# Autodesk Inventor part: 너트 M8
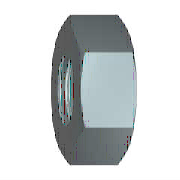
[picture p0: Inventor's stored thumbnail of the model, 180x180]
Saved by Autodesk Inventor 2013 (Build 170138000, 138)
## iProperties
IsCustomPart: 1
Created: 2012-02
Part Number: 너트 M8
Material: 강철, 연강
Description: 6각 너트 및 6각 가는 너트
Document SubType Name: Modeling
Standard: KS B 1012
Designer: mduedu
Standards Organization: KS
Language: ko-KR
Size Designation: M 8
Categories: <MemberInstance><Categories><Category DisplayName="조임쇠" InternalName="e4da775c-781d-43d5-af7c-5136215cf5a6" Mnemonic="FSTN"><Category DisplayName="너트" InternalN
Density: 1 g/cm^3
Author: mduedu
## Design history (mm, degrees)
sketch "스케치1"
  geometry: L1 (-7.506, 0)-(-3.753, 6.5); L2 (-3.753, 6.5)-(3.753, 6.5); L3 (3.753, 6.5)-(7.506, 0); L4 (7.506, 0)-(3.753, -6.5); L5 (3.753, -6.5)-(-3.753, -6.5); L6 (-3.753, -6.5)-(-7.506, 0); 2 further points
  constraints: 12 end point, 1 coincident, 1 horizontal, 11 other
  dimensions: "d0" = 15.01111 distance of L3.end L1.start (= 1.1547 x SW)
extrude "본체" new body sketch "스케치1" distance "d1" = 5 (= KOH); taper "d2" = 0 deg
sketch "스케치2"
  geometry: L1 (0, 3.753)-(0, 7.506) reference; L2 (0, 7.506)-(5, 7.506) reference; L3 (5, 3.753)-(5, 7.506) reference; L4 (-1, 0)-(6, 0) reference; L5 (0.581, 7.506)-(0, 6.5); L6 (4.419, 7.506)-(5, 6.5)
  constraints: 4 end point, 4 point on line
  dimensions: "d3" = 30 deg angle of L1 L5 (= ANG1); "d4" = 30 deg angle of L3 L6 (= ANG2); "d5" = 13 diameter of L5.end L4 (= SW0); "d6" = 13 diameter of L6.end L4 (= SW01)
revolve "모따기1" sketch "스케치2" stored, may be unused: angle "d7" = 90 deg
sketch "스케치3"
  geometry: A1 r 6.5 centre (0, 0) between (-3.25, -5.629) and (3.25, -5.629) reference; 1 further point
  constraints: 1 coincident
hole "스레드" sketch "스케치3" at (0, 0) diameter "d25" = 6.647; stored, may be unused: countersink angle "d29" = 82 deg, drill point angle "d31" = 118 deg; dims "d26" = 6, "d27" = 4, "d28" = 2, "d30" = 8
workaxis "Work Axis1"
workplane "Work Plane1"
body "Solid1"
chamfer "모따기2" distance "d8" = 0.67658 (= -0.5 x GD1 + 0.5 x NND); stored, may be unused: angle "d9" = 30 deg, second distance "d40" = 0.67658 (= -0.5 x GD1 + 0.5 x NND)
chamfer "모따기3" distance "d10" = 0.67658 (= -0.5 x GD1 + 0.5 x NND); stored, may be unused: angle "d11" = 30 deg, second distance "d41" = 0.67658 (= -0.5 x GD1 + 0.5 x NND)
other parameters: "ANG1" = 30 deg [user parameter; used in 1 equation term], "ANG2" = 30 deg [user parameter; used in 1 equation term], "NND" = 8 [user parameter; used in 4 equation terms], "KOH" = 5 [user parameter; used in 1 equation term], "SW" = 13 [user parameter; used in 4 equation terms], "SW0" = 13 (= SW) [user parameter; used in 1 equation term], "SW01" = 13 (= SW) [user parameter; used in 1 equation term], "GD1" = 6.64684 (computed from THREADDIA, PTC, TOA) [user parameter; used in 4 equation terms], "d13" = 0, "d14" = 0, "d39" = 0, "d42" = 0, "GUL" = 0.67658 (= 0.541266 x PTC) [user parameter], "TPU" = 8 (computed from PTC) [user parameter], "THREADDIA" = 8 [user parameter; used in 1 equation term], "TOA" = 30 deg [user parameter; used in 1 equation term], "PTC" = 1.25 [user parameter; used in 4 equation terms], "E0" = 15.015 (= 1.155 x SW) [user parameter], "GAL" = 0.67658 (= 0.541266 x PTC) [user parameter]
